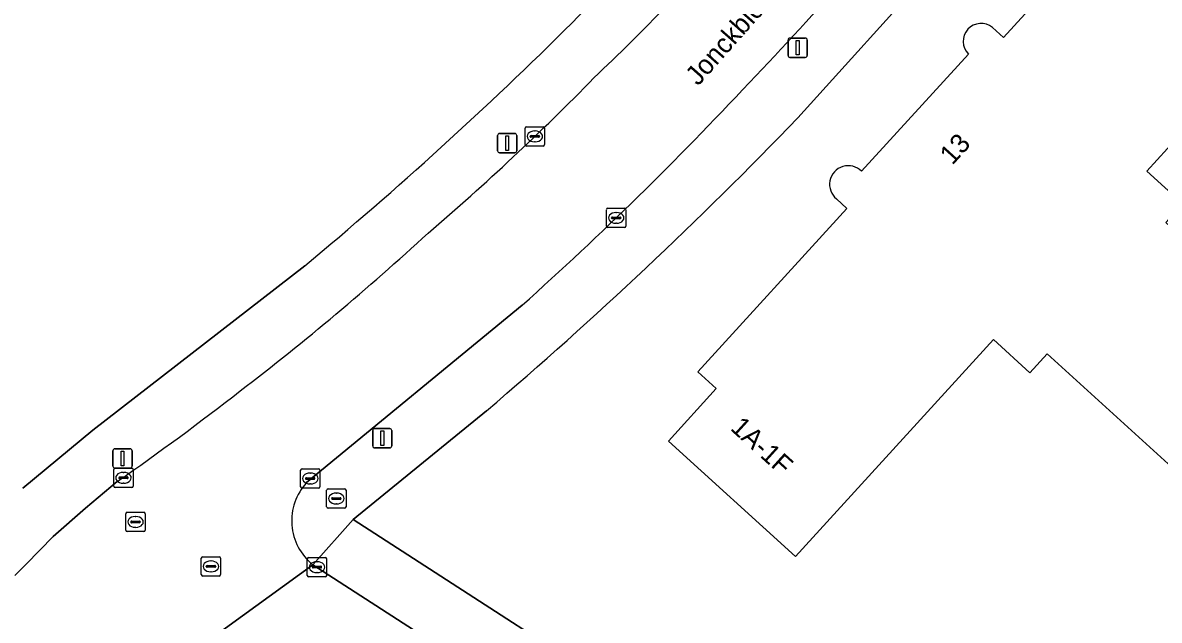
# Model space of a CAD drawing. Extents: x 161139 to 161601, y 381708 to 382245.
# Drawn here: x 161296.5 to 161355.3, y 382078.8 to 382109.7 of the extents above; entities that cross this region are included whole.
import ezdxf

# ---------------------------------------------------------------- set-up
doc = ezdxf.new("R2010")
doc.units = 0
for name, color, linetype in [('IMGEO_Brandkraan', 7, 'Continuous'), ('IMGEO_Erf', 7, 'Continuous'), ('IMGEO_Groenvoorziening', 7, 'Continuous'), ('IMGEO_Kolk', 7, 'Continuous'), ('IMGEO_Lichtmast', 7, 'Continuous'), ('IMGEO_Openbare_ruimte_label', 7, 'Continuous'), ('IMGEO_Pand', 7, 'Continuous'), ('IMGEO_Pand_nummerreeks', 7, 'Continuous'), ('IMGEO_Rijbaan_lokaal_open', 7, 'Continuous'), ('IMGEO_Rioolput', 7, 'Continuous'), ('IMGEO_Voetpad_open', 7, 'Continuous')]:
    doc.layers.add(name, color=color, linetype=linetype)

msp = doc.modelspace()

# ---------------------------------------------------------------- linework, layer by layer
at = {"layer": 'IMGEO_Brandkraan'}
for p, q in [((161312.257, 382084.662), (161312.257, 382085.514)), ((161312.332, 382085.588), (161313.184, 382085.588)), ((161312.745, 382085.368), (161312.77, 382085.368)), ((161313.258, 382085.514), (161313.258, 382084.662)), ((161312.516, 382085.082), (161312.516, 382085.094)), ((161312.954, 382085.045), (161312.556, 382085.045)), ((161312.559, 382085.131), (161312.957, 382085.131)), ((161312.768, 382084.808), (161312.743, 382084.808)), ((161313, 382085.094), (161313, 382085.082)), ((161313.184, 382084.588), (161312.332, 382084.588))]:
    msp.add_line(p, q, dxfattribs=at)
for points in [[(161312.257, 382084.662), (161312.257, 382085.514)], [(161312.332, 382085.588), (161313.184, 382085.588)], [(161313.258, 382085.514), (161313.258, 382084.662)], [(161313.184, 382084.588), (161312.332, 382084.588)]]:
    msp.add_lwpolyline(points, dxfattribs=at)
for centre, radius, start, end in [((161312.334, 382085.512), 0.0765, 91.55205, 178.44795), ((161312.334, 382085.512), 0.0765, 91.55205, 178.44795), ((161313.182, 382085.512), 0.0765, 1.55205, 88.44795), ((161313.182, 382085.512), 0.0765, 1.55205, 88.44795), ((161312.556, 382085.091), 0.0403, 85.87752, 175.75265), ((161312.553, 382085.081), 0.0366, 178.93798, 274.71019), ((161312.957, 382085.088), 0.043, 264.86636, 352.45326), ((161312.961, 382085.093), 0.0386, 1.73085, 96.63898), ((161312.334, 382084.664), 0.0765, 181.55205, 268.44795), ((161312.334, 382084.664), 0.0765, 181.55205, 268.44795), ((161313.182, 382084.664), 0.0765, 271.55205, 358.44795), ((161313.182, 382084.664), 0.0765, 271.55205, 358.44795)]:
    msp.add_arc(centre, radius, start, end, dxfattribs=at)
for centre, major_axis, ratio, start_param, end_param in [((161312.744, 382085.088), (-0.387, 0.002), 0.722429, 4.712389, 7.853982), ((161312.769, 382085.088), (-0.39, 0.002), 0.717154, 1.570796, 4.712389)]:
    msp.add_ellipse(centre, major_axis=major_axis, ratio=ratio, start_param=start_param, end_param=end_param, dxfattribs=at)
at = {"layer": 'IMGEO_Erf'}
for points in [[(161320.525, 382089.631), (161313.623, 382083.997), (161443.483, 382000), (161462.38, 381987.777), (161470.3, 382000), (161498.24, 382043.117), (161359.011, 382133.266)], [(161346.685, 382109.457), (161347.252, 382108.941), (161354.956, 382117.404), (161355.81, 382116.625), (161358.18, 382119.228), (161364.817, 382113.186), (161354.661, 382102.03), (161356.521, 382100.336), (161355.647, 382099.376), (161364.97, 382090.887), (161358.81, 382084.121)], [(161343.639, 382112.574), (161336.623, 382104.782)], [(161339.916, 382102.024), (161345.438, 382108.089)], [(161358.81, 382084.121), (161349.515, 382092.582), (161348.62, 382091.598), (161346.729, 382093.319), (161336.5, 382082.084), (161329.934, 382088.061), (161332.405, 382090.775), (161331.456, 382091.639), (161339.157, 382100.098), (161338.619, 382100.588)]]:
    msp.add_lwpolyline(points, dxfattribs=at)
for centre, radius, start, end in [((161346.091, 382108.746), 0.926, 50.1574, 225.14114), ((161172.719, 382262.803), 227.673, 310.48144, 316.04693), ((161339.23, 382101.34), 0.969, 44.93046, 230.89263)]:
    msp.add_arc(centre, radius, start, end, dxfattribs=at)
at = {"layer": 'IMGEO_Groenvoorziening'}
for points in [[(161324.958, 382109.709), (161332.601, 382117.82), (161335.947, 382121.635)], [(161300.166, 382088.62), (161311.125, 382097.133)], [(161296.542, 382085.619), (161300.166, 382088.62)]]:
    msp.add_lwpolyline(points, dxfattribs=at)
msp.add_arc((161176.676, 382258.917), 210.358, 309.72807, 314.82178, dxfattribs=at)
at = {"layer": 'IMGEO_Kolk'}
for p, q in [((161322.522, 382103.402), (161322.522, 382104.254)), ((161322.597, 382104.328), (161323.449, 382104.328)), ((161323.523, 382104.254), (161323.523, 382103.402)), ((161322.781, 382103.822), (161322.781, 382103.834)), ((161323.219, 382103.785), (161322.821, 382103.785)), ((161322.824, 382103.871), (161323.222, 382103.871)), ((161323.01, 382104.108), (161323.035, 382104.108)), ((161323.265, 382103.834), (161323.265, 382103.822)), ((161323.449, 382103.328), (161322.597, 382103.328)), ((161323.033, 382103.548), (161323.008, 382103.548)), ((161326.803, 382100.109), (161327.655, 382100.109)), ((161326.728, 382099.183), (161326.728, 382100.035)), ((161326.987, 382099.603), (161326.987, 382099.615)), ((161327.425, 382099.566), (161327.027, 382099.566)), ((161327.03, 382099.652), (161327.428, 382099.652)), ((161327.216, 382099.889), (161327.241, 382099.889)), ((161327.471, 382099.615), (161327.471, 382099.603)), ((161327.729, 382100.035), (161327.729, 382099.183)), ((161327.655, 382099.109), (161326.803, 382099.109)), ((161327.239, 382099.329), (161327.214, 382099.329)), ((161301.251, 382085.734), (161301.251, 382086.586)), ((161301.326, 382086.66), (161302.178, 382086.66)), ((161302.252, 382086.586), (161302.252, 382085.734)), ((161310.909, 382085.698), (161310.909, 382086.55)), ((161310.984, 382086.624), (161311.836, 382086.624)), ((161311.91, 382086.55), (161311.91, 382085.698)), ((161301.51, 382086.154), (161301.51, 382086.166)), ((161301.948, 382086.117), (161301.55, 382086.117)), ((161301.553, 382086.203), (161301.951, 382086.203)), ((161301.739, 382086.44), (161301.764, 382086.44)), ((161301.994, 382086.166), (161301.994, 382086.154)), ((161311.168, 382086.118), (161311.168, 382086.13)), ((161311.606, 382086.081), (161311.208, 382086.081)), ((161311.211, 382086.167), (161311.609, 382086.167)), ((161311.397, 382086.404), (161311.422, 382086.404)), ((161311.652, 382086.13), (161311.652, 382086.118)), ((161302.178, 382085.66), (161301.326, 382085.66)), ((161301.762, 382085.88), (161301.737, 382085.88)), ((161311.836, 382085.624), (161310.984, 382085.624)), ((161311.42, 382085.844), (161311.395, 382085.844)), ((161311.256, 382081.112), (161311.256, 382081.964)), ((161311.331, 382082.038), (161312.183, 382082.038)), ((161312.257, 382081.964), (161312.257, 382081.112)), ((161311.515, 382081.532), (161311.515, 382081.544)), ((161311.953, 382081.495), (161311.555, 382081.495)), ((161311.558, 382081.581), (161311.956, 382081.581)), ((161311.767, 382081.258), (161311.742, 382081.258)), ((161311.744, 382081.818), (161311.769, 382081.818)), ((161311.999, 382081.544), (161311.999, 382081.532)), ((161312.183, 382081.038), (161311.331, 382081.038))]:
    msp.add_line(p, q, dxfattribs=at)
for points in [[(161322.522, 382103.402), (161322.522, 382104.254)], [(161322.597, 382104.328), (161323.449, 382104.328)], [(161323.523, 382104.254), (161323.523, 382103.402)], [(161323.449, 382103.328), (161322.597, 382103.328)], [(161326.803, 382100.109), (161327.655, 382100.109)], [(161326.728, 382099.183), (161326.728, 382100.035)], [(161327.729, 382100.035), (161327.729, 382099.183)], [(161327.655, 382099.109), (161326.803, 382099.109)], [(161301.251, 382085.734), (161301.251, 382086.586)], [(161301.326, 382086.66), (161302.178, 382086.66)], [(161302.252, 382086.586), (161302.252, 382085.734)], [(161310.909, 382085.698), (161310.909, 382086.55)], [(161310.984, 382086.624), (161311.836, 382086.624)], [(161311.91, 382086.55), (161311.91, 382085.698)], [(161302.178, 382085.66), (161301.326, 382085.66)], [(161311.836, 382085.624), (161310.984, 382085.624)], [(161311.256, 382081.112), (161311.256, 382081.964)], [(161311.331, 382082.038), (161312.183, 382082.038)], [(161312.257, 382081.964), (161312.257, 382081.112)], [(161312.183, 382081.038), (161311.331, 382081.038)]]:
    msp.add_lwpolyline(points, dxfattribs=at)
for centre, radius, start, end in [((161322.599, 382104.252), 0.0765, 91.55205, 178.44795), ((161322.599, 382104.252), 0.0765, 91.55205, 178.44795), ((161323.447, 382104.252), 0.0765, 1.55205, 88.44795), ((161323.447, 382104.252), 0.0765, 1.55205, 88.44795), ((161322.821, 382103.831), 0.0403, 85.87752, 175.75265), ((161322.818, 382103.821), 0.0366, 178.93798, 274.71019), ((161323.222, 382103.828), 0.043, 264.86636, 352.45326), ((161323.226, 382103.833), 0.0386, 1.73085, 96.63898), ((161322.599, 382103.404), 0.0765, 181.55205, 268.44795), ((161322.599, 382103.404), 0.0765, 181.55205, 268.44795), ((161323.447, 382103.404), 0.0765, 271.55205, 358.44795), ((161323.447, 382103.404), 0.0765, 271.55205, 358.44795), ((161326.805, 382100.033), 0.0765, 91.55205, 178.44795), ((161326.805, 382100.033), 0.0765, 91.55205, 178.44795), ((161327.653, 382100.033), 0.0765, 1.55205, 88.44795), ((161327.653, 382100.033), 0.0765, 1.55205, 88.44795), ((161327.027, 382099.612), 0.0403, 85.87752, 175.75265), ((161327.024, 382099.602), 0.0366, 178.93798, 274.71019), ((161327.428, 382099.609), 0.043, 264.86636, 352.45326), ((161327.432, 382099.614), 0.0386, 1.73085, 96.63898), ((161326.805, 382099.185), 0.0765, 181.55205, 268.44795), ((161326.805, 382099.185), 0.0765, 181.55205, 268.44795), ((161327.653, 382099.185), 0.0765, 271.55205, 358.44795), ((161327.653, 382099.185), 0.0765, 271.55205, 358.44795), ((161301.328, 382086.584), 0.0765, 91.55205, 178.44795), ((161301.328, 382086.584), 0.0765, 91.55205, 178.44795), ((161302.176, 382086.584), 0.0765, 1.55205, 88.44795), ((161302.176, 382086.584), 0.0765, 1.55205, 88.44795), ((161310.986, 382086.548), 0.0765, 91.55205, 178.44795), ((161310.986, 382086.548), 0.0765, 91.55205, 178.44795), ((161311.834, 382086.548), 0.0765, 1.55205, 88.44795), ((161311.834, 382086.548), 0.0765, 1.55205, 88.44795), ((161301.55, 382086.163), 0.0403, 85.87752, 175.75265), ((161301.547, 382086.153), 0.0366, 178.93798, 274.71019), ((161301.951, 382086.16), 0.043, 264.86636, 352.45326), ((161301.955, 382086.165), 0.0386, 1.73085, 96.63898), ((161311.208, 382086.127), 0.0403, 85.87752, 175.75265), ((161311.205, 382086.117), 0.0366, 178.93798, 274.71019), ((161311.609, 382086.124), 0.043, 264.86636, 352.45326), ((161311.613, 382086.129), 0.0386, 1.73085, 96.63898), ((161301.328, 382085.736), 0.0765, 181.55205, 268.44795), ((161301.328, 382085.736), 0.0765, 181.55205, 268.44795), ((161302.176, 382085.736), 0.0765, 271.55205, 358.44795), ((161302.176, 382085.736), 0.0765, 271.55205, 358.44795), ((161310.986, 382085.7), 0.0765, 181.55205, 268.44795), ((161310.986, 382085.7), 0.0765, 181.55205, 268.44795), ((161311.834, 382085.7), 0.0765, 271.55205, 358.44795), ((161311.834, 382085.7), 0.0765, 271.55205, 358.44795), ((161311.333, 382081.962), 0.0765, 91.55205, 178.44795), ((161311.333, 382081.962), 0.0765, 91.55205, 178.44795), ((161312.181, 382081.962), 0.0765, 1.55205, 88.44795), ((161312.181, 382081.962), 0.0765, 1.55205, 88.44795), ((161311.555, 382081.541), 0.0403, 85.87752, 175.75265), ((161311.552, 382081.531), 0.0366, 178.93798, 274.71019), ((161311.956, 382081.538), 0.043, 264.86636, 352.45326), ((161311.96, 382081.543), 0.0386, 1.73085, 96.63898), ((161311.333, 382081.114), 0.0765, 181.55205, 268.44795), ((161311.333, 382081.114), 0.0765, 181.55205, 268.44795), ((161312.181, 382081.114), 0.0765, 271.55205, 358.44795), ((161312.181, 382081.114), 0.0765, 271.55205, 358.44795)]:
    msp.add_arc(centre, radius, start, end, dxfattribs=at)
for centre, major_axis, ratio, start_param, end_param in [((161323.009, 382103.828), (-0.387, 0.002), 0.722429, 4.712389, 7.853982), ((161323.034, 382103.828), (-0.39, 0.002), 0.717154, 1.570796, 4.712389), ((161327.215, 382099.609), (-0.387, 0.002), 0.722429, 4.712389, 7.853982), ((161327.24, 382099.609), (-0.39, 0.002), 0.717154, 1.570796, 4.712389), ((161301.738, 382086.16), (-0.387, 0.002), 0.722429, 4.712389, 7.853982), ((161301.763, 382086.16), (-0.39, 0.002), 0.717154, 1.570796, 4.712389), ((161311.396, 382086.124), (-0.387, 0.002), 0.722429, 4.712389, 7.853982), ((161311.421, 382086.124), (-0.39, 0.002), 0.717154, 1.570796, 4.712389), ((161311.743, 382081.538), (-0.387, 0.002), 0.722429, 4.712389, 7.853982), ((161311.768, 382081.538), (-0.39, 0.002), 0.717154, 1.570796, 4.712389)]:
    msp.add_ellipse(centre, major_axis=major_axis, ratio=ratio, start_param=start_param, end_param=end_param, dxfattribs=at)
at = {"layer": 'IMGEO_Lichtmast'}
for p, q in [((161336.214, 382108.914), (161337.004, 382108.914)), ((161337.004, 382108.914), (161336.214, 382108.914)), ((161336.114, 382108.014), (161336.114, 382108.814)), ((161336.114, 382108.814), (161336.114, 382108.014)), ((161337.104, 382108.814), (161337.104, 382108.014)), ((161337.104, 382108.014), (161337.104, 382108.814)), ((161337.004, 382107.914), (161336.214, 382107.914)), ((161336.214, 382107.914), (161337.004, 382107.914)), ((161321.094, 382103.077), (161321.094, 382103.877)), ((161321.094, 382103.877), (161321.094, 382103.077)), ((161321.194, 382103.977), (161321.984, 382103.977)), ((161321.984, 382103.977), (161321.194, 382103.977)), ((161322.084, 382103.877), (161322.084, 382103.077)), ((161322.084, 382103.077), (161322.084, 382103.877)), ((161321.984, 382102.977), (161321.194, 382102.977)), ((161321.194, 382102.977), (161321.984, 382102.977)), ((161314.636, 382087.81), (161314.636, 382088.61)), ((161314.636, 382088.61), (161314.636, 382087.81)), ((161314.736, 382088.71), (161315.526, 382088.71)), ((161315.526, 382088.71), (161314.736, 382088.71)), ((161315.626, 382088.61), (161315.626, 382087.81)), ((161315.626, 382087.81), (161315.626, 382088.61)), ((161301.204, 382086.762), (161301.204, 382087.562)), ((161301.204, 382087.562), (161301.204, 382086.762)), ((161301.304, 382087.662), (161302.094, 382087.662)), ((161302.094, 382087.662), (161301.304, 382087.662)), ((161302.194, 382087.562), (161302.194, 382086.762)), ((161302.194, 382086.762), (161302.194, 382087.562)), ((161315.526, 382087.71), (161314.736, 382087.71)), ((161314.736, 382087.71), (161315.526, 382087.71)), ((161302.094, 382086.662), (161301.304, 382086.662)), ((161301.304, 382086.662), (161302.094, 382086.662))]:
    msp.add_line(p, q, dxfattribs=at)
for points in [[(161336.534, 382108.789), (161336.684, 382108.789), (161336.684, 382108.039), (161336.534, 382108.039), (161336.534, 382108.789)], [(161321.514, 382103.852), (161321.664, 382103.852), (161321.664, 382103.102), (161321.514, 382103.102), (161321.514, 382103.852)], [(161315.056, 382088.585), (161315.206, 382088.585), (161315.206, 382087.835), (161315.056, 382087.835), (161315.056, 382088.585)], [(161301.624, 382087.537), (161301.774, 382087.537), (161301.774, 382086.787), (161301.624, 382086.787), (161301.624, 382087.537)]]:
    msp.add_lwpolyline(points, dxfattribs=at)
for centre, start, end in [((161336.214, 382108.814), 90, 180), ((161336.214, 382108.814), 90, 180), ((161337.004, 382108.814), 0, 90), ((161337.004, 382108.814), 360, 90), ((161336.214, 382108.014), 180, 270), ((161336.214, 382108.014), 180, 270), ((161337.004, 382108.014), 270, 0), ((161337.004, 382108.014), 270, 0), ((161321.194, 382103.877), 90, 180), ((161321.194, 382103.877), 90, 180), ((161321.984, 382103.877), 0, 90), ((161321.984, 382103.877), 360, 90), ((161321.194, 382103.077), 180, 270), ((161321.194, 382103.077), 180, 270), ((161321.984, 382103.077), 270, 0), ((161321.984, 382103.077), 270, 0), ((161314.736, 382088.61), 90, 180), ((161314.736, 382088.61), 90, 180), ((161315.526, 382088.61), 0, 90), ((161315.526, 382088.61), 360, 90), ((161314.736, 382087.81), 180, 270), ((161314.736, 382087.81), 180, 270), ((161315.526, 382087.81), 270, 0), ((161315.526, 382087.81), 270, 0), ((161301.304, 382087.562), 90, 180), ((161301.304, 382087.562), 90, 180), ((161302.094, 382087.562), 0, 90), ((161302.094, 382087.562), 360, 90), ((161301.304, 382086.762), 180, 270), ((161301.304, 382086.762), 180, 270), ((161302.094, 382086.762), 270, 0), ((161302.094, 382086.762), 270, 0)]:
    msp.add_arc(centre, 0.1, start, end, dxfattribs=at)
at = {"layer": 'IMGEO_Pand'}
for points in [[(161338.619, 382100.588), (161339.157, 382100.098), (161331.456, 382091.639), (161332.405, 382090.775), (161329.934, 382088.061), (161336.5, 382082.084), (161346.729, 382093.319), (161348.62, 382091.598), (161349.515, 382092.582), (161358.81, 382084.121), (161364.97, 382090.887), (161355.647, 382099.376), (161356.521, 382100.336), (161354.661, 382102.03), (161364.817, 382113.186), (161358.18, 382119.228), (161355.81, 382116.625), (161354.956, 382117.404), (161347.252, 382108.941), (161346.685, 382109.457)], [(161345.438, 382108.089), (161339.916, 382102.024)]]:
    msp.add_lwpolyline(points, dxfattribs=at)
for centre, radius, start, end in [((161346.091, 382108.746), 0.926, 50.1574, 225.14114), ((161339.23, 382101.34), 0.969, 44.93046, 230.89263)]:
    msp.add_arc(centre, radius, start, end, dxfattribs=at)
at = {"layer": 'IMGEO_Rijbaan_lokaal_open'}
for points in [[(161311.219, 382085.909), (161322.359, 382095.085)], [(161301.43, 382085.969), (161299.791, 382084.592), (161298.12, 382083.125), (161296.722, 382081.694), (161296.127, 382081.099)], [(161375.585, 382040.285), (161362.411, 382048.813), (161356.674, 382052.498), (161311.536, 382081.664), (161306.338, 382077.878), (161325.321, 382065.668), (161328.504, 382063.628), (161339.032, 382056.795), (161345.442, 382052.667), (161359.944, 382043.32), (161366.307, 382039.161), (161381.679, 382029.228), (161388.068, 382025.069), (161398.439, 382018.395)], [(161306.338, 382077.878), (161311.536, 382081.664)]]:
    msp.add_lwpolyline(points, dxfattribs=at)
for centre, radius, start, end in [((161186.941, 382247.202), 203.531, 316.31175, 320.59327), ((161247.867, 382189.45), 113.75, 313.43897, 318.80017), ((161232.187, 382198.512), 131.212, 310.55768, 315.69018), ((161201.158, 382230.421), 181.674, 311.8463, 317.04167), ((161224.09, 382200.103), 137.781, 307.40615, 312.68589), ((161217.789, 382206.042), 146.333, 304.86058, 307.95362), ((161313.371, 382083.935), 2.92, 137.47045, 231.07095)]:
    msp.add_arc(centre, radius, start, end, dxfattribs=at)
at = {"layer": 'IMGEO_Rioolput'}
for p, q in [((161301.873, 382083.451), (161301.873, 382084.303)), ((161301.948, 382084.377), (161302.8, 382084.377)), ((161302.874, 382084.303), (161302.874, 382083.451)), ((161302.132, 382083.871), (161302.132, 382083.883)), ((161302.57, 382083.834), (161302.172, 382083.834)), ((161302.175, 382083.92), (161302.573, 382083.92)), ((161302.361, 382084.157), (161302.386, 382084.157)), ((161302.616, 382083.883), (161302.616, 382083.871)), ((161302.8, 382083.377), (161301.948, 382083.377)), ((161302.384, 382083.597), (161302.359, 382083.597)), ((161305.775, 382081.151), (161305.775, 382082.003)), ((161305.85, 382082.077), (161306.702, 382082.077)), ((161306.263, 382081.857), (161306.288, 382081.857)), ((161306.776, 382082.003), (161306.776, 382081.151)), ((161306.034, 382081.571), (161306.034, 382081.583)), ((161306.472, 382081.534), (161306.074, 382081.534)), ((161306.077, 382081.62), (161306.475, 382081.62)), ((161306.286, 382081.297), (161306.261, 382081.297)), ((161306.518, 382081.583), (161306.518, 382081.571)), ((161306.702, 382081.077), (161305.85, 382081.077))]:
    msp.add_line(p, q, dxfattribs=at)
for points in [[(161301.873, 382083.451), (161301.873, 382084.303)], [(161301.948, 382084.377), (161302.8, 382084.377)], [(161302.874, 382084.303), (161302.874, 382083.451)], [(161302.8, 382083.377), (161301.948, 382083.377)], [(161305.775, 382081.151), (161305.775, 382082.003)], [(161305.85, 382082.077), (161306.702, 382082.077)], [(161306.776, 382082.003), (161306.776, 382081.151)], [(161306.702, 382081.077), (161305.85, 382081.077)]]:
    msp.add_lwpolyline(points, dxfattribs=at)
for centre, radius, start, end in [((161301.95, 382084.301), 0.0765, 91.55205, 178.44795), ((161301.95, 382084.301), 0.0765, 91.55205, 178.44795), ((161302.798, 382084.301), 0.0765, 1.55205, 88.44795), ((161302.798, 382084.301), 0.0765, 1.55205, 88.44795), ((161302.172, 382083.88), 0.0403, 85.87752, 175.75265), ((161302.169, 382083.87), 0.0366, 178.93798, 274.71019), ((161302.573, 382083.877), 0.043, 264.86636, 352.45326), ((161302.577, 382083.882), 0.0386, 1.73085, 96.63898), ((161301.95, 382083.453), 0.0765, 181.55205, 268.44795), ((161301.95, 382083.453), 0.0765, 181.55205, 268.44795), ((161302.798, 382083.453), 0.0765, 271.55205, 358.44795), ((161302.798, 382083.453), 0.0765, 271.55205, 358.44795), ((161305.852, 382082.001), 0.0765, 91.55205, 178.44795), ((161305.852, 382082.001), 0.0765, 91.55205, 178.44795), ((161306.7, 382082.001), 0.0765, 1.55205, 88.44795), ((161306.7, 382082.001), 0.0765, 1.55205, 88.44795), ((161306.074, 382081.58), 0.0403, 85.87752, 175.75265), ((161306.071, 382081.57), 0.0366, 178.93798, 274.71019), ((161306.475, 382081.577), 0.043, 264.86636, 352.45326), ((161306.479, 382081.582), 0.0386, 1.73085, 96.63898), ((161305.852, 382081.153), 0.0765, 181.55205, 268.44795), ((161305.852, 382081.153), 0.0765, 181.55205, 268.44795), ((161306.7, 382081.153), 0.0765, 271.55205, 358.44795), ((161306.7, 382081.153), 0.0765, 271.55205, 358.44795)]:
    msp.add_arc(centre, radius, start, end, dxfattribs=at)
for centre, major_axis, ratio, start_param, end_param in [((161302.36, 382083.877), (-0.387, 0.002), 0.722429, 4.712389, 7.853982), ((161302.385, 382083.877), (-0.39, 0.002), 0.717154, 1.570796, 4.712389), ((161306.262, 382081.577), (-0.387, 0.002), 0.722429, 4.712389, 7.853982), ((161306.287, 382081.577), (-0.39, 0.002), 0.717154, 1.570796, 4.712389)]:
    msp.add_ellipse(centre, major_axis=major_axis, ratio=ratio, start_param=start_param, end_param=end_param, dxfattribs=at)
at = {"layer": 'IMGEO_Voetpad_open'}
for points in [[(161335.947, 382121.635), (161332.601, 382117.82), (161324.958, 382109.709)], [(161336.623, 382104.782), (161343.639, 382112.574)], [(161311.125, 382097.133), (161300.166, 382088.62), (161296.542, 382085.619)], [(161322.359, 382095.085), (161311.219, 382085.909)], [(161311.536, 382081.664), (161313.623, 382083.997), (161320.525, 382089.631)], [(161296.127, 382081.099), (161296.722, 382081.694), (161298.12, 382083.125), (161299.791, 382084.592), (161301.43, 382085.969)], [(161313.623, 382083.997), (161311.536, 382081.664), (161356.674, 382052.498), (161362.411, 382048.813), (161375.585, 382040.285), (161382.572, 382035.748), (161395.928, 382027.083), (161402.927, 382022.535), (161416.852, 382013.552), (161420.042, 382011.494), (161421.741, 382010.379), (161425.551, 382007.922), (161458.647, 381986.439), (161460.91, 381984.988)], [(161464.955, 381985.959), (161462.38, 381987.777), (161443.483, 382000), (161313.623, 382083.997)]]:
    msp.add_lwpolyline(points, dxfattribs=at)
for centre, radius, start, end in [((161186.941, 382247.202), 203.531, 316.31175, 320.59327), ((161247.867, 382189.45), 113.75, 313.43897, 318.80017), ((161176.676, 382258.917), 210.358, 309.72807, 314.82178), ((161232.187, 382198.512), 131.212, 310.55768, 315.69018), ((161201.158, 382230.421), 181.674, 311.8463, 317.04167), ((161172.719, 382262.803), 227.673, 310.48144, 316.04693), ((161224.09, 382200.103), 137.781, 307.40615, 312.68589), ((161217.789, 382206.042), 146.333, 304.86058, 307.95362), ((161313.371, 382083.935), 2.92, 137.47045, 231.07095)]:
    msp.add_arc(centre, radius, start, end, dxfattribs=at)

# ---------------------------------------------------------------- texts
at = {"layer": 'IMGEO_Openbare_ruimte_label'}
msp.add_text('Jonckbloetlaan', height=1, rotation=48.48538, dxfattribs=at).set_placement((161331.465, 382106.401))
at = {"layer": 'IMGEO_Pand_nummerreeks'}
for s, rotation, p in [('13', 47.68308, (161344.607, 382102.305)), ('1A-1F', 317.75911, (161333.082, 382088.674))]:
    msp.add_text(s, height=1, rotation=rotation, dxfattribs=at).set_placement(p)

doc.saveas('drawing.dxf')
